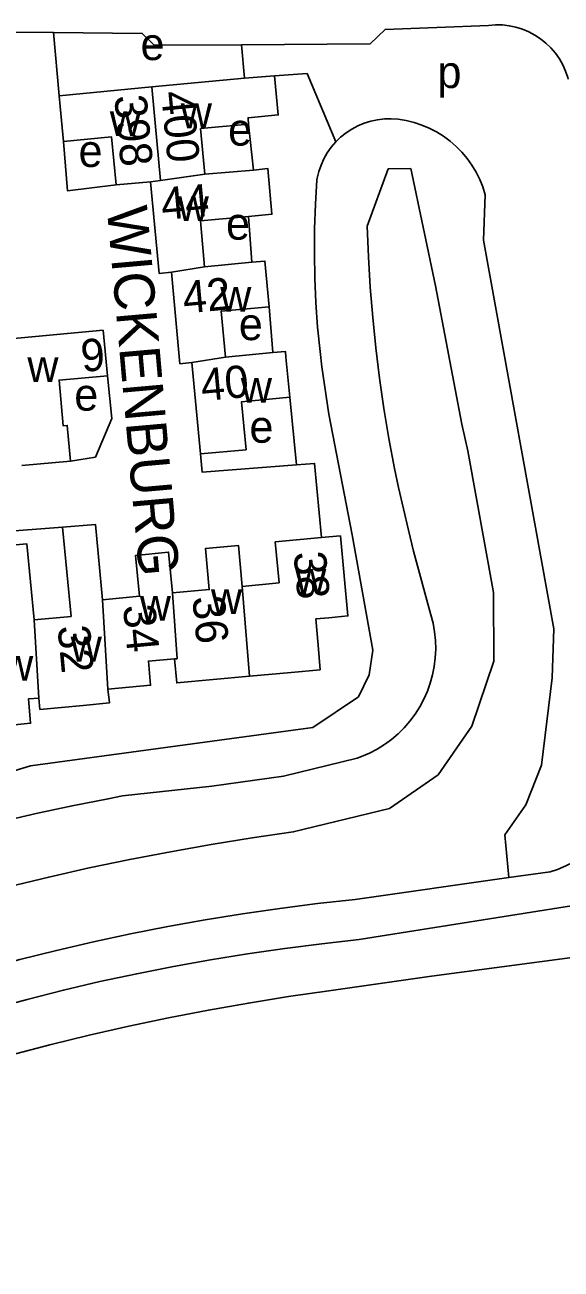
# Model space of a CAD drawing. Extents: x 157794 to 159375, y 380877 to 382306.
# Drawn here: x 158462.3 to 158528.8, y 381105.8 to 381260.1 of the extents above; entities that cross this region are included whole.
import ezdxf

# ---------------------------------------------------------------- set-up
doc = ezdxf.new("R2010")
doc.units = 0
for name, color, linetype in [('BLT_Basislijn', 7, 'Continuous'), ('BLT_Bebouwing', 7, 'Continuous'), ('BLT_Centroide', 7, 'Continuous'), ('BLT_Huisnummer', 7, 'Continuous'), ('BLT_Huisnummer_ tussenligend', 7, 'Continuous'), ('BLT_Onderverdeling_panden', 7, 'Continuous'), ('BLT_Straatnaam', 7, 'Continuous')]:
    doc.layers.add(name, color=color, linetype=linetype)

msp = doc.modelspace()

# ---------------------------------------------------------------- linework, layer by layer
at = {"layer": 'BLT_Basislijn'}
for p, q in [((158465.86, 381259.18), (158459.25, 381259.25)), ((158465.86, 381259.18), (158466.57, 381251.35)), ((158489.53, 381253.51), (158489.17, 381257.68)), ((158490.47, 381230.69), (158490.03, 381236.37)), ((158493.04, 381219.48), (158492.6, 381225.16)), ((158495.99, 381205.57), (158495.15, 381213.96)), ((158440.69, 381195.84), (158466.95, 381197.84)), ((158505.46, 381182.58), (158502.89, 381196.89)), ((158522.35, 381154.35), (158521.83, 381159.66)), ((158522.35, 381154.35), (158503.28, 381151.64)), ((158527.48, 381155.08), (158522.35, 381154.35))]:
    msp.add_line(p, q, dxfattribs=at)
for points in [[(158489.17, 381257.68), (158478.34, 381257.6), (158476.86, 381259.08), (158465.86, 381259.18)], [(158519.83, 381260.07), (158506.99, 381259.58), (158505.15, 381257.8), (158489.17, 381257.68)], [(158519.83, 381260.07), (158520.68, 381260.13), (158521.53, 381260.12), (158522.38, 381260.02), (158523.21, 381259.85), (158524.02, 381259.59), (158524.81, 381259.27), (158525.56, 381258.86), (158526.28, 381258.4), (158526.94, 381257.86), (158527.55, 381257.27), (158528.11, 381256.62), (158528.6, 381255.92), (158529.02, 381255.18), (158529.37, 381254.41), (158529.65, 381253.6), (158529.7, 381253.4)], [(158493.28, 381253.8), (158497.3, 381254.12), (158500.86, 381245.61)], [(158508.6, 381248.43), (158507.75, 381248.49), (158506.89, 381248.47), (158506.04, 381248.37), (158505.21, 381248.2), (158504.39, 381247.94), (158503.6, 381247.61), (158502.85, 381247.21), (158502.14, 381246.74), (158501.47, 381246.2), (158500.86, 381245.61)], [(158508.6, 381248.43), (158509.6, 381248.27), (158510.58, 381248.03), (158511.54, 381247.71), (158512.47, 381247.32), (158513.37, 381246.86), (158514.23, 381246.32), (158515.05, 381245.72), (158515.81, 381245.06), (158516.52, 381244.34), (158517.17, 381243.57), (158517.76, 381242.74), (158518.28, 381241.88), (158518.73, 381240.97), (158519.11, 381240.03), (158519.41, 381239.07), (158519.2, 381233.43)], [(158490.66, 381242.13), (158490.06, 381247.82)], [(158467.1, 381245.67), (158467.57, 381239.55), (158473.62, 381240.28)], [(158500.86, 381245.61), (158500.31, 381244.96), (158499.81, 381244.26), (158499.39, 381243.52), (158499.04, 381242.74), (158498.76, 381241.93), (158498.56, 381241.1), (158498.53, 381240.93)], [(158510.19, 381242.32), (158507.38, 381242.27), (158504.77, 381235.17), (158504.91, 381231.38), (158505.14, 381227.6), (158505.45, 381223.83), (158505.83, 381220.06), (158506.3, 381216.3), (158506.84, 381212.56), (158507.46, 381208.82), (158508.17, 381205.1), (158508.65, 381202.76)], [(158510.19, 381242.32), (158513.23, 381227.77), (158516.52, 381210.62), (158517.24, 381207.3), (158520.43, 381189.72), (158520.47, 381181.2), (158517.75, 381173.12), (158513.55, 381167.11), (158507.52, 381162.93)], [(158498.53, 381240.93), (158498.34, 381237.88), (158498.24, 381234.83), (158498.21, 381231.78), (158498.27, 381228.73), (158498.41, 381225.69), (158498.62, 381222.64), (158498.92, 381219.61), (158499.14, 381217.71)], [(158519.2, 381233.43), (158527.93, 381185.21)], [(158499.14, 381217.71), (158500, 381211.86), (158502.89, 381196.89)], [(158472.54, 381216.61), (158473.07, 381211.29), (158471.05, 381206.5), (158467.98, 381206.03)], [(158484.09, 381206.91), (158484.3, 381204.64), (158495.99, 381205.57)], [(158499.08, 381196.55), (158498.24, 381205.74), (158495.99, 381205.57)], [(158508.65, 381202.76), (158509.89, 381197.47)], [(158509.89, 381197.47), (158510.5, 381194.85), (158512.66, 381186.95)], [(158512.66, 381186.95), (158512.93, 381185.91), (158513.12, 381184.85), (158513.23, 381183.78), (158513.26, 381182.7), (158513.21, 381181.63), (158513.08, 381180.56), (158512.87, 381179.51), (158512.59, 381178.47), (158512.23, 381177.46), (158511.79, 381176.47), (158511.28, 381175.53), (158510.7, 381174.62), (158510.06, 381173.76), (158509.36, 381172.94), (158508.59, 381172.19), (158507.77, 381171.49), (158506.91, 381170.85), (158505.99, 381170.28), (158505.04, 381169.78), (158504.06, 381169.36), (158503.53, 381169.16)], [(158527.93, 381185.21), (158527.69, 381179.12), (158526.38, 381168.29), (158524.45, 381163.39), (158521.83, 381159.66)], [(158505.46, 381182.58), (158505, 381179.52), (158503.68, 381176.79), (158498.04, 381172.99), (158462.98, 381168.23), (158424.71, 381156.55), (158392.37, 381142.52), (158337.15, 381105.79)], [(158503.53, 381169.16), (158494.39, 381166.94), (158485.5, 381165.7), (158474.4, 381164.48)], [(158416.12, 381146.68), (158420.31, 381148.48), (158424.53, 381150.2), (158428.78, 381151.85), (158433.06, 381153.42), (158437.37, 381154.92), (158441.7, 381156.34), (158446.06, 381157.69), (158450.43, 381158.96), (158454.84, 381160.15), (158459.26, 381161.26), (158463.7, 381162.3), (158468.15, 381163.26), (158472.63, 381164.14), (158474.4, 381164.48)], [(158507.52, 381162.93), (158495.6, 381160.02), (158490.51, 381159.28), (158485.43, 381158.47), (158480.37, 381157.57), (158475.32, 381156.6), (158470.29, 381155.55), (158465.27, 381154.42), (158460.27, 381153.21), (158455.29, 381151.93), (158450.33, 381150.57), (158445.39, 381149.13), (158443.03, 381148.41)], [(158534.02, 381158.96), (158533.19, 381158.2), (158532.31, 381157.5), (158531.39, 381156.86), (158530.42, 381156.29), (158529.41, 381155.8), (158528.37, 381155.37), (158527.48, 381155.08)], [(158503.28, 381151.64), (158498.61, 381151.12), (158493.94, 381150.53), (158489.29, 381149.86), (158484.65, 381149.11), (158480.02, 381148.28), (158475.41, 381147.38), (158470.82, 381146.39), (158466.24, 381145.33), (158461.68, 381144.19), (158457.14, 381142.97), (158452.62, 381141.67), (158448.13, 381140.3), (158443.66, 381138.85), (158439.21, 381137.33), (158434.79, 381135.73), (158430.4, 381134.05), (158426.04, 381132.3), (158422.8, 381130.94)], [(158503.78, 381146.66), (158531.93, 381151.12), (158533.54, 381145.03)], [(158503.78, 381146.66), (158499.15, 381146.15), (158494.53, 381145.57), (158489.92, 381144.9), (158485.32, 381144.15), (158480.74, 381143.33), (158476.17, 381142.43), (158471.62, 381141.45), (158467.08, 381140.39), (158462.57, 381139.25), (158458.07, 381138.04), (158453.6, 381136.74), (158449.14, 381135.38), (158444.72, 381133.93), (158440.31, 381132.41), (158435.94, 381130.82), (158431.59, 381129.15), (158427.27, 381127.4), (158424.76, 381126.34)], [(158530.2, 381144.45), (158512.76, 381142.13), (158500, 381140.31)], [(158500, 381140.31), (158495.01, 381139.59), (158490.04, 381138.79), (158485.07, 381137.91), (158480.13, 381136.95), (158475.2, 381135.91), (158470.28, 381134.8), (158465.39, 381133.61), (158460.51, 381132.33), (158455.65, 381130.99), (158450.82, 381129.56), (158446.01, 381128.06), (158441.22, 381126.48), (158440.32, 381126.17)]]:
    msp.add_lwpolyline(points, dxfattribs=at)
at = {"layer": 'BLT_Bebouwing'}
for p, q in [((158489.53, 381253.51), (158478.05, 381252.43)), ((158493.28, 381253.8), (158489.53, 381253.51)), ((158478.05, 381252.43), (158466.57, 381251.35)), ((158490.66, 381242.13), (158484.63, 381241.6)), ((158477.89, 381240.67), (158473.62, 381240.28)), ((158490.47, 381230.69), (158484.6, 381230.14)), ((158493.04, 381219.48), (158487.19, 381218.93)), ((158484.09, 381206.91), (158483.03, 381218.24)), ((158461.93, 381205.48), (158467.98, 381206.03))]:
    msp.add_line(p, q, dxfattribs=at)
for points in [[(158490.06, 381247.82), (158490, 381248.53), (158489.99, 381248.62), (158493.73, 381248.97), (158493.28, 381253.8)], [(158466.57, 381251.35), (158466.7, 381250), (158467.1, 381245.67)], [(158484.63, 381241.6), (158484.1, 381247.26), (158490.06, 381247.82)], [(158473.62, 381240.28), (158473.06, 381246.23), (158467.1, 381245.67)], [(158490.03, 381236.37), (158492.95, 381236.64), (158492.42, 381242.33), (158490.66, 381242.13)], [(158480.47, 381229.44), (158478.98, 381229.3), (158477.89, 381240.67)], [(158484.6, 381230.14), (158484.07, 381235.81), (158490.03, 381236.37)], [(158492.6, 381225.16), (158492.07, 381230.84), (158490.47, 381230.69)], [(158483.03, 381218.24), (158481.54, 381218.1), (158480.47, 381229.44)], [(158487.19, 381218.93), (158486.65, 381224.6), (158492.6, 381225.16)], [(158472.54, 381216.61), (158472, 381222.26), (158460.51, 381221.2), (158460.65, 381219.71)], [(158495.15, 381213.96), (158494.69, 381218.93), (158494.62, 381219.63), (158493.04, 381219.48)], [(158467.98, 381206.03), (158467.56, 381210.45), (158467.05, 381210.4), (158466.55, 381216.08), (158472.54, 381216.61)], [(158495.15, 381213.96), (158489.19, 381213.39), (158489.75, 381207.42), (158484.09, 381206.91)], [(158463.46, 381186.32), (158468.03, 381186.75), (158466.95, 381197.84)], [(158466.95, 381197.84), (158471.06, 381198.17), (158471.95, 381188.82)], [(158454.95, 381183.93), (158459.52, 381184.37), (158458.46, 381195.37), (158462.54, 381195.77), (158463.46, 381186.32)], [(158489.26, 381190.48), (158493.84, 381190.92), (158493.35, 381196), (158499.08, 381196.55)], [(158490.15, 381179.34), (158495.32, 381179.81), (158498.93, 381180.13), (158498.67, 381183.2), (158498.4, 381186.44), (158500, 381186.59), (158502.38, 381186.82), (158501.91, 381191.79), (158501.44, 381196.77)], [(158501.44, 381196.77), (158500, 381196.64), (158499.08, 381196.55)], [(158471.95, 381188.82), (158476.53, 381189.26), (158476.03, 381194.32), (158480.12, 381194.73), (158480.61, 381189.66)], [(158480.61, 381189.66), (158485.18, 381190.09), (158484.7, 381195.17), (158488.78, 381195.56), (158489.26, 381190.48)], [(158472.6, 381177.73), (158477.9, 381178.21), (158477.63, 381181.21), (158480.88, 381181.51)], [(158480.88, 381181.51), (158481.15, 381178.5), (158490.15, 381179.34)], [(158464.03, 381176.63), (158464.16, 381175.22), (158469.55, 381175.72), (158472.79, 381176.02), (158472.6, 381177.73)], [(158455.5, 381174.23), (158455.63, 381172.82), (158455.89, 381169.98), (158456.47, 381169.64), (158458.23, 381169.81), (158458.7, 381170.42), (158458.44, 381173.08), (158461.03, 381173.32), (158463.02, 381173.5), (158462.74, 381176.51), (158464.03, 381176.63)]]:
    msp.add_lwpolyline(points, dxfattribs=at)
at = {"layer": 'BLT_Onderverdeling_panden'}
for p, q in [((158478.05, 381252.43), (158479.14, 381240.84)), ((158477.89, 381240.67), (158479.14, 381240.84)), ((158479.14, 381240.84), (158484.63, 381241.6)), ((158480.47, 381229.44), (158484.6, 381230.14)), ((158487.19, 381218.93), (158483.03, 381218.24)), ((158489.26, 381190.48), (158490.15, 381179.34)), ((158471.95, 381188.82), (158472.6, 381177.73)), ((158463.46, 381186.32), (158464.03, 381176.63))]:
    msp.add_line(p, q, dxfattribs=at)
msp.add_lwpolyline([(158480.61, 381189.66), (158481.18, 381181.51), (158480.88, 381181.51)], dxfattribs=at)

# ---------------------------------------------------------------- texts
at = {"layer": 'BLT_Centroide'}
for s, p in [('e', (158476.65, 381255.77)), ('p', (158513.48, 381252.3)), ('w', (158481.64, 381247.31)), ('w', (158472.84, 381246.34)), ('e', (158487.51, 381245.16)), ('e', (158468.96, 381242.51)), ('w', (158481.26, 381235.81)), ('e', (158487.25, 381233.49)), ('w', (158486.53, 381224.56)), ('e', (158488.84, 381221.03)), ('w', (158462.61, 381215.84)), ('w', (158489.09, 381213.25)), ('e', (158468.43, 381212.28)), ('e', (158490.16, 381208.3)), ('w', (158495.83, 381189.58)), ('w', (158485.38, 381187.06)), ('w', (158476.56, 381186.23)), ('w', (158467.98, 381181.16)), ('w', (158459.48, 381178.78))]:
    msp.add_text(s, height=4, dxfattribs=at).set_placement(p)
at = {"layer": 'BLT_Huisnummer'}
for s, rotation, p in [('398', 275.457, (158473.38, 381251.3)), ('400', 275.457, (158479.19, 381251.78)), ('44', 5.199, (158479.36, 381235.92)), ('9', 5.0572, (158469.41, 381217.07)), ('40', 5.199, (158484.29, 381213.46)), ('38', 275.2953, (158495.62, 381194.67)), ('34', 275.2953, (158474.47, 381188.08))]:
    msp.add_text(s, height=4, rotation=rotation, dxfattribs=at).set_placement(p)
at = {"layer": 'BLT_Huisnummer_ tussenligend'}
for s, rotation, p in [('42', 5.199, (158482.05, 381224.32)), ('36', 275.2953, (158483.07, 381189.14)), ('32', 275.2953, (158466.35, 381185.5))]:
    msp.add_text(s, height=4, rotation=rotation, dxfattribs=at).set_placement(p)
at = {"layer": 'BLT_Straatnaam'}
msp.add_text('WICKENBURG', height=5, rotation=275.0531, dxfattribs=at).set_placement((158472.46, 381237.45))

doc.saveas('drawing.dxf')
